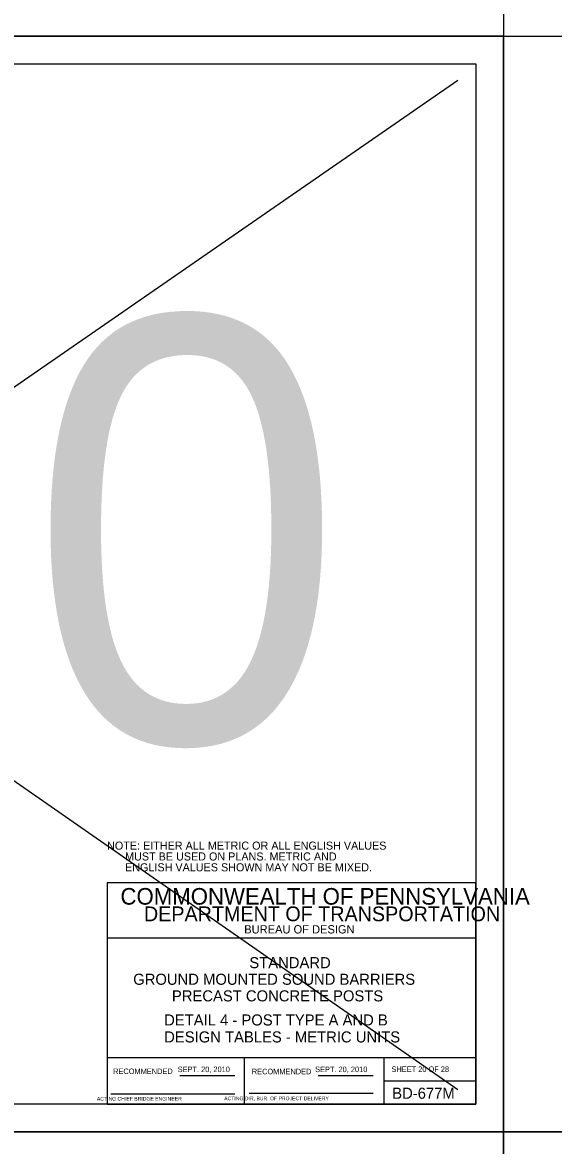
# Model space of a CAD drawing. Extents: x 3351 to 8430, y -3586 to 1457.
# Drawn here: x 6023 to 6311, y -2406 to -1797 of the extents above; entities that cross this region are included whole.
import ezdxf

# ---------------------------------------------------------------- set-up
doc = ezdxf.new("R2010")
doc.units = 0
for name, color, linetype in [('1', 7, 'Continuous'), ('2', 7, 'Continuous'), ('PLT-BNDY', 7, 'Continuous')]:
    doc.layers.add(name, color=color, linetype=linetype)

msp = doc.modelspace()

# ---------------------------------------------------------------- linework, layer by layer
at = {"layer": '1'}
for p, q in [((5471.04, -1826.93), (6259.47, -2375.42)), ((5474.44, -2370.88), (6259.47, -1828.07))]:
    msp.add_line(p, q, dxfattribs=at)
at = {"layer": '2'}
for p, q in [((5483.34, -1819.31), (6269.34, -1819.31)), ((6269.34, -1819.31), (6269.34, -2383.31)), ((6269.34, -2263.31), (6069.34, -2263.31)), ((6069.34, -2263.31), (6069.34, -2383.31)), ((6269.34, -2383.31), (6269.34, -2263.31)), ((6269.34, -2293.31), (6069.34, -2293.31)), ((6269.34, -2358.31), (6069.34, -2358.31)), ((6143.84, -2383.31), (6143.84, -2358.31)), ((6219.34, -2358.31), (6219.34, -2383.31)), ((6108.81, -2367.81), (6138.57, -2367.81)), ((6183.81, -2367.81), (6213.71, -2367.81)), ((6219.34, -2370.81), (6269.34, -2370.81)), ((6071.34, -2377.81), (6138.57, -2377.81)), ((6146.47, -2377.43), (6213.71, -2377.43)), ((6269.34, -2383.31), (5483.34, -2383.31)), ((6069.34, -2383.31), (6269.34, -2383.31))]:
    msp.add_line(p, q, dxfattribs=at)
at = {"layer": 'PLT-BNDY'}
for points in [[(5443.34, -1210.31), (6284.34, -1210.31), (6284.34, -1804.31), (5443.34, -1804.31)], [(5443.34, -1804.31), (6284.34, -1804.31), (6284.34, -2398.31), (5443.34, -2398.31)], [(6284.34, -1804.31), (7125.34, -1804.31), (7125.34, -2398.31), (6284.34, -2398.31)], [(5443.34, -2398.31), (6284.34, -2398.31), (6284.34, -2992.31), (5443.34, -2992.31)], [(6284.34, -2398.31), (7125.34, -2398.31), (7125.34, -2992.31), (6284.34, -2992.31)]]:
    msp.add_lwpolyline(points, close=True, dxfattribs=at)

# ---------------------------------------------------------------- texts
at = {"layer": '1'}
for s, height, p in [('20', 230.4, (5855.29, -2187.1)), ('STANDARD', 6, (6146.48, -2309.64)), ('GROUND MOUNTED SOUND BARRIERS', 6, (6083.5, -2318.64)), ('PRECAST CONCRETE POSTS', 6, (6104.5, -2327.64)), ('DETAIL 4 - POST TYPE A AND B', 6, (6100.29, -2340.71)), ('DESIGN TABLES - METRIC UNITS', 6, (6100.31, -2349.91)), ('SHEET 20 OF 28', 3, (6223.59, -2365.92)), ('BD-677M', 6, (6223.97, -2380.43))]:
    msp.add_text(s, height=height, dxfattribs=at).set_placement(p)
at = {"layer": '2'}
for s, height, p in [('NOTE: EITHER ALL METRIC OR ALL ENGLISH VALUES', 4.375, (6069.34, -2245.37)), ('      MUST BE USED ON PLANS. METRIC AND', 4.375, (6069.34, -2251.24)), ('      ENGLISH VALUES SHOWN MAY NOT BE MIXED.', 4.375, (6069.34, -2257.12)), ('COMMONWEALTH OF PENNSYLVANIA', 9, (6076.59, -2275.18)), ('DEPARTMENT OF TRANSPORTATION', 8.0002, (6089.34, -2284.18)), ('BUREAU OF DESIGN', 4.5, (6143.72, -2290.81)), ('SEPT. 20, 2010', 3, (6107.61, -2366)), ('       ACTING CHIEF BRIDGE ENGINEER', 2.0002, (6058.43, -2381.43)), ('   ACTING DIR, BUR. OF PROJECT DELIVERY', 2.0002, (6130.53, -2381.25))]:
    msp.add_text(s, height=height, dxfattribs=at).set_placement(p)
for s, p in [('RECOMMENDED', (6072.61, -2367.06)), ('RECOMMENDED', (6147.83, -2367.18)), ('SEPT. 20, 2010', (6182.16, -2366))]:
    msp.add_text(s, height=3, rotation=360, dxfattribs=at).set_placement(p)

doc.saveas('drawing.dxf')
